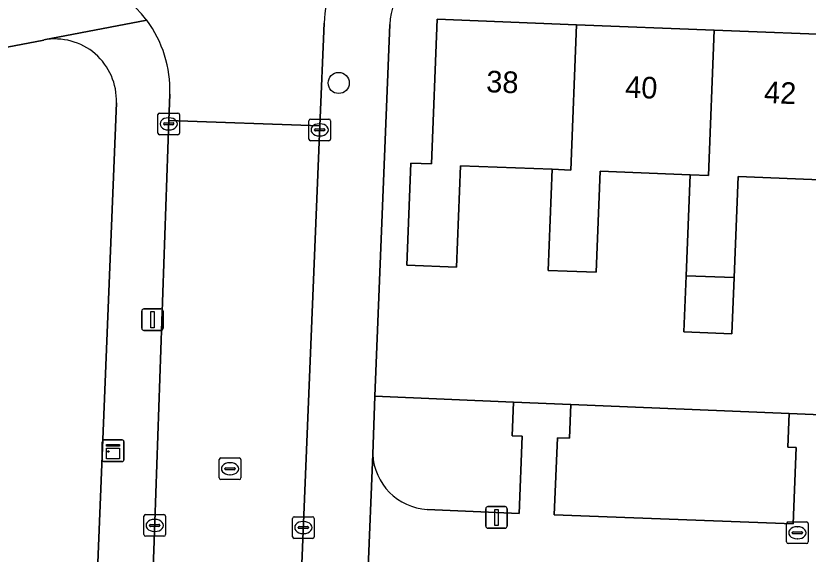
# Model space of a CAD drawing. Extents: x 160077 to 160948, y 386481 to 387498.
# Drawn here: x 160670.27 to 160706.93, y 386759.71 to 386784.61 of the extents above; entities that cross this region are included whole.
import ezdxf

# ---------------------------------------------------------------- set-up
doc = ezdxf.new("R2010")
doc.units = 0
for name, color, linetype in [('IMGEO_Boom', 7, 'Continuous'), ('IMGEO_Erf', 7, 'Continuous'), ('IMGEO_Groenvoorziening', 7, 'Continuous'), ('IMGEO_Kast', 7, 'Continuous'), ('IMGEO_Kolk', 7, 'Continuous'), ('IMGEO_Lichtmast', 7, 'Continuous'), ('IMGEO_Pand', 7, 'Continuous'), ('IMGEO_Pand_nummerreeks', 7, 'Continuous'), ('IMGEO_Rijbaan_lokaal_open', 7, 'Continuous'), ('IMGEO_Rioolput', 7, 'Continuous'), ('IMGEO_Voetpad_open', 7, 'Continuous')]:
    doc.layers.add(name, color=color, linetype=linetype)

msp = doc.modelspace()

# ---------------------------------------------------------------- linework, layer by layer
at = {"layer": 'IMGEO_Boom'}
msp.add_circle((160685.214, 386781.508), 0.489, dxfattribs=at)
at = {"layer": 'IMGEO_Erf'}
for points in [[(160707.857, 386777.016), (160703.69, 386777.179), (160703.506, 386772.502), (160703.404, 386769.907), (160701.185, 386769.994), (160701.287, 386772.588), (160701.47, 386777.264), (160697.303, 386777.427), (160697.119, 386772.75), (160695.776, 386772.802), (160694.9, 386772.836), (160695.083, 386777.512), (160690.847, 386777.678), (160690.663, 386772.991), (160688.367, 386773.081), (160688.55, 386777.798), (160689.499, 386777.761), (160689.76, 386784.455), (160696.221, 386784.203), (160702.59, 386783.955), (160708.959, 386783.707)], [(160687.571, 386784.21), (160686.882, 386767.017), (160693.294, 386766.741), (160695.949, 386766.63), (160706.046, 386766.21), (160708.637, 386766.106), (160727.336, 386765.387), (160726.211, 386772.948), (160726.016, 386772.942), (160716.258, 386773.261), (160714.11, 386773.331), (160714.131, 386773.869), (160709.963, 386774.033), (160709.893, 386772.254), (160708.514, 386772.307), (160707.674, 386772.34), (160707.857, 386777.016)], [(160671.565, 386783.492), (160627.292, 386775.05)], [(160624.696, 386772.042), (160624.053, 386756.457), (160635.418, 386756.081), (160656.069, 386755.397), (160656.152, 386757.908), (160661.06, 386757.745), (160665.846, 386757.587), (160665.763, 386755.076), (160673.888, 386754.75), (160674.925, 386780.592)]]:
    msp.add_lwpolyline(points, dxfattribs=at)
for centre, radius, start, end in [((160690.549, 386784.091), 2.981, 100.7384, 177.7207), ((160672.096, 386780.71), 2.832, 357.6061, 100.7993)]:
    msp.add_arc(centre, radius, start, end, dxfattribs=at)
at = {"layer": 'IMGEO_Groenvoorziening'}
for points in [[(160693.702, 386765.165), (160693.232, 386765.185), (160693.294, 386766.741), (160686.882, 386767.017), (160686.785, 386764.329)], [(160689.312, 386761.774), (160693.559, 386761.591), (160693.702, 386765.165)]]:
    msp.add_lwpolyline(points, dxfattribs=at)
msp.add_lwpolyline([(160695.949, 386766.63), (160695.887, 386765.074), (160695.33, 386765.097), (160695.187, 386761.53), (160706.234, 386761.114), (160706.375, 386764.638), (160705.984, 386764.654), (160706.046, 386766.21)], close=True, dxfattribs=at)
msp.add_arc((160689.475, 386764.462), 2.693, 182.8284, 266.5402, dxfattribs=at)
at = {"layer": 'IMGEO_Kast'}
for p, q in [((160674.276, 386764.068), (160674.276, 386764.909)), ((160674.276, 386764.909), (160674.276, 386764.068)), ((160674.351, 386764.993), (160675.192, 386764.993)), ((160675.192, 386764.993), (160674.351, 386764.993)), ((160675.276, 386764.918), (160675.276, 386764.077)), ((160675.276, 386764.077), (160675.276, 386764.918)), ((160675.201, 386763.993), (160674.36, 386763.993)), ((160674.36, 386763.993), (160675.201, 386763.993))]:
    msp.add_line(p, q, dxfattribs=at)
for points in [[(160674.471, 386764.783), (160675.071, 386764.783), (160675.071, 386764.698), (160674.471, 386764.698), (160674.471, 386764.783)], [(160674.471, 386764.608), (160675.071, 386764.608), (160675.071, 386764.119), (160674.471, 386764.119), (160674.471, 386764.608)]]:
    msp.add_lwpolyline(points, dxfattribs=at)
msp.add_circle((160674.555, 386764.457), 0.0377, dxfattribs=at)
for centre, start, end in [((160674.354, 386764.915), 92.4484, 184.2845), ((160674.354, 386764.915), 92.4484, 184.2845), ((160675.198, 386764.915), 2.4484, 94.2845), ((160675.198, 386764.915), 2.4484, 94.2845), ((160674.354, 386764.071), 182.4484, 274.2845), ((160674.354, 386764.071), 182.4484, 274.2845), ((160675.198, 386764.071), 272.4484, 4.2845), ((160675.198, 386764.071), 272.4484, 4.2845)]:
    msp.add_arc(centre, 0.0779, start, end, dxfattribs=at)
at = {"layer": 'IMGEO_Kolk'}
for p, q in [((160676.849, 386779.189), (160676.849, 386780.041)), ((160676.924, 386780.115), (160677.776, 386780.115)), ((160677.337, 386779.895), (160677.362, 386779.895)), ((160677.85, 386780.041), (160677.85, 386779.189)), ((160677.108, 386779.609), (160677.108, 386779.621)), ((160677.546, 386779.572), (160677.148, 386779.572)), ((160677.151, 386779.658), (160677.549, 386779.658)), ((160677.592, 386779.621), (160677.592, 386779.609)), ((160683.832, 386778.911), (160683.832, 386779.763)), ((160683.907, 386779.837), (160684.759, 386779.837)), ((160684.32, 386779.617), (160684.345, 386779.617)), ((160684.833, 386779.763), (160684.833, 386778.911)), ((160677.36, 386779.335), (160677.335, 386779.335)), ((160684.091, 386779.331), (160684.091, 386779.343)), ((160684.529, 386779.294), (160684.131, 386779.294)), ((160684.134, 386779.38), (160684.532, 386779.38)), ((160684.575, 386779.343), (160684.575, 386779.331)), ((160677.776, 386779.115), (160676.924, 386779.115)), ((160684.759, 386778.837), (160683.907, 386778.837)), ((160684.343, 386779.057), (160684.318, 386779.057)), ((160676.273, 386761.537), (160677.125, 386761.537)), ((160676.198, 386760.611), (160676.198, 386761.463)), ((160676.686, 386761.317), (160676.711, 386761.317)), ((160677.199, 386761.463), (160677.199, 386760.611)), ((160683.076, 386760.513), (160683.076, 386761.365)), ((160683.151, 386761.439), (160684.003, 386761.439)), ((160683.564, 386761.219), (160683.589, 386761.219)), ((160684.077, 386761.365), (160684.077, 386760.513)), ((160706.005, 386761.198), (160706.857, 386761.198)), ((160676.457, 386761.031), (160676.457, 386761.043)), ((160676.895, 386760.994), (160676.497, 386760.994)), ((160676.5, 386761.08), (160676.898, 386761.08)), ((160676.941, 386761.043), (160676.941, 386761.031)), ((160683.335, 386760.933), (160683.335, 386760.945)), ((160683.773, 386760.896), (160683.375, 386760.896)), ((160683.378, 386760.982), (160683.776, 386760.982)), ((160683.819, 386760.945), (160683.819, 386760.933)), ((160705.93, 386760.272), (160705.93, 386761.124)), ((160706.418, 386760.978), (160706.443, 386760.978)), ((160706.931, 386761.124), (160706.931, 386760.272)), ((160677.125, 386760.537), (160676.273, 386760.537)), ((160676.709, 386760.757), (160676.684, 386760.757)), ((160684.003, 386760.439), (160683.151, 386760.439)), ((160683.587, 386760.659), (160683.562, 386760.659)), ((160706.189, 386760.692), (160706.189, 386760.704)), ((160706.627, 386760.655), (160706.229, 386760.655)), ((160706.232, 386760.741), (160706.63, 386760.741)), ((160706.673, 386760.704), (160706.673, 386760.692)), ((160706.857, 386760.198), (160706.005, 386760.198)), ((160706.441, 386760.418), (160706.416, 386760.418))]:
    msp.add_line(p, q, dxfattribs=at)
for points in [[(160676.849, 386779.189), (160676.849, 386780.041)], [(160676.924, 386780.115), (160677.776, 386780.115)], [(160677.85, 386780.041), (160677.85, 386779.189)], [(160683.832, 386778.911), (160683.832, 386779.763)], [(160683.907, 386779.837), (160684.759, 386779.837)], [(160684.833, 386779.763), (160684.833, 386778.911)], [(160677.776, 386779.115), (160676.924, 386779.115)], [(160684.759, 386778.837), (160683.907, 386778.837)], [(160676.273, 386761.537), (160677.125, 386761.537)], [(160676.198, 386760.611), (160676.198, 386761.463)], [(160677.199, 386761.463), (160677.199, 386760.611)], [(160683.076, 386760.513), (160683.076, 386761.365)], [(160683.151, 386761.439), (160684.003, 386761.439)], [(160684.077, 386761.365), (160684.077, 386760.513)], [(160706.005, 386761.198), (160706.857, 386761.198)], [(160705.93, 386760.272), (160705.93, 386761.124)], [(160706.931, 386761.124), (160706.931, 386760.272)], [(160677.125, 386760.537), (160676.273, 386760.537)], [(160684.003, 386760.439), (160683.151, 386760.439)], [(160706.857, 386760.198), (160706.005, 386760.198)]]:
    msp.add_lwpolyline(points, dxfattribs=at)
for centre, radius, start, end in [((160676.926, 386780.039), 0.0765, 91.552, 178.448), ((160676.926, 386780.039), 0.0765, 91.552, 178.448), ((160677.774, 386780.039), 0.0765, 1.552, 88.448), ((160677.774, 386780.039), 0.0765, 1.552, 88.448), ((160677.148, 386779.618), 0.0403, 85.8775, 175.7526), ((160677.145, 386779.608), 0.0366, 178.938, 274.7102), ((160677.549, 386779.615), 0.043, 264.8664, 352.4533), ((160677.553, 386779.62), 0.0386, 1.7309, 96.639), ((160683.909, 386779.761), 0.0765, 91.552, 178.448), ((160683.909, 386779.761), 0.0765, 91.552, 178.448), ((160684.757, 386779.761), 0.0765, 1.552, 88.448), ((160684.757, 386779.761), 0.0765, 1.552, 88.448), ((160676.926, 386779.191), 0.0765, 181.552, 268.448), ((160676.926, 386779.191), 0.0765, 181.552, 268.448), ((160677.774, 386779.191), 0.0765, 271.552, 358.448), ((160677.774, 386779.191), 0.0765, 271.552, 358.448), ((160684.131, 386779.34), 0.0403, 85.8775, 175.7526), ((160684.128, 386779.33), 0.0366, 178.938, 274.7102), ((160684.532, 386779.337), 0.043, 264.8664, 352.4533), ((160684.536, 386779.342), 0.0386, 1.7309, 96.639), ((160683.909, 386778.913), 0.0765, 181.552, 268.448), ((160683.909, 386778.913), 0.0765, 181.552, 268.448), ((160684.757, 386778.913), 0.0765, 271.552, 358.448), ((160684.757, 386778.913), 0.0765, 271.552, 358.448), ((160676.275, 386761.461), 0.0765, 91.552, 178.448), ((160676.275, 386761.461), 0.0765, 91.552, 178.448), ((160677.123, 386761.461), 0.0765, 1.552, 88.448), ((160677.123, 386761.461), 0.0765, 1.552, 88.448), ((160683.153, 386761.363), 0.0765, 91.552, 178.448), ((160683.153, 386761.363), 0.0765, 91.552, 178.448), ((160684.001, 386761.363), 0.0765, 1.552, 88.448), ((160684.001, 386761.363), 0.0765, 1.552, 88.448), ((160706.007, 386761.122), 0.0765, 91.552, 178.448), ((160706.007, 386761.122), 0.0765, 91.552, 178.448), ((160706.855, 386761.122), 0.0765, 1.552, 88.448), ((160706.855, 386761.122), 0.0765, 1.552, 88.448), ((160676.497, 386761.04), 0.0403, 85.8775, 175.7526), ((160676.494, 386761.03), 0.0366, 178.938, 274.7102), ((160676.898, 386761.037), 0.043, 264.8664, 352.4533), ((160676.902, 386761.042), 0.0386, 1.7309, 96.639), ((160683.375, 386760.942), 0.0403, 85.8775, 175.7526), ((160683.372, 386760.932), 0.0366, 178.938, 274.7102), ((160683.776, 386760.939), 0.043, 264.8664, 352.4533), ((160683.78, 386760.944), 0.0386, 1.7309, 96.639), ((160676.275, 386760.613), 0.0765, 181.552, 268.448), ((160676.275, 386760.613), 0.0765, 181.552, 268.448), ((160677.123, 386760.613), 0.0765, 271.552, 358.448), ((160677.123, 386760.613), 0.0765, 271.552, 358.448), ((160683.153, 386760.515), 0.0765, 181.552, 268.448), ((160683.153, 386760.515), 0.0765, 181.552, 268.448), ((160684.001, 386760.515), 0.0765, 271.552, 358.448), ((160684.001, 386760.515), 0.0765, 271.552, 358.448), ((160706.229, 386760.701), 0.0403, 85.8775, 175.7526), ((160706.226, 386760.691), 0.0366, 178.938, 274.7102), ((160706.63, 386760.698), 0.043, 264.8664, 352.4533), ((160706.634, 386760.703), 0.0386, 1.7309, 96.639), ((160706.007, 386760.274), 0.0765, 181.552, 268.448), ((160706.007, 386760.274), 0.0765, 181.552, 268.448), ((160706.855, 386760.274), 0.0765, 271.552, 358.448), ((160706.855, 386760.274), 0.0765, 271.552, 358.448)]:
    msp.add_arc(centre, radius, start, end, dxfattribs=at)
for centre, major_axis, ratio, start_param, end_param in [((160677.336, 386779.615), (-0.387, 0.002), 0.722429, 4.712389, 7.853982), ((160677.361, 386779.615), (-0.39, 0.002), 0.717154, 1.570796, 4.712389), ((160684.319, 386779.337), (-0.387, 0.002), 0.722429, 4.712389, 7.853982), ((160684.344, 386779.337), (-0.39, 0.002), 0.717154, 1.570796, 4.712389), ((160676.685, 386761.037), (-0.387, 0.002), 0.722429, 4.712389, 7.853982), ((160676.71, 386761.037), (-0.39, 0.002), 0.717154, 1.570796, 4.712389), ((160683.563, 386760.939), (-0.387, 0.002), 0.722429, 4.712389, 7.853982), ((160683.588, 386760.939), (-0.39, 0.002), 0.717154, 1.570796, 4.712389), ((160706.417, 386760.698), (-0.387, 0.002), 0.722429, 4.712389, 7.853982), ((160706.442, 386760.698), (-0.39, 0.002), 0.717154, 1.570796, 4.712389)]:
    msp.add_ellipse(centre, major_axis=major_axis, ratio=ratio, start_param=start_param, end_param=end_param, dxfattribs=at)
at = {"layer": 'IMGEO_Lichtmast'}
for p, q in [((160676.2, 386771.057), (160676.99, 386771.057)), ((160676.99, 386771.057), (160676.2, 386771.057)), ((160676.1, 386770.157), (160676.1, 386770.957)), ((160676.1, 386770.957), (160676.1, 386770.157)), ((160677.09, 386770.957), (160677.09, 386770.157)), ((160677.09, 386770.157), (160677.09, 386770.957)), ((160676.99, 386770.057), (160676.2, 386770.057)), ((160676.2, 386770.057), (160676.99, 386770.057)), ((160692.116, 386761.906), (160692.906, 386761.906)), ((160692.906, 386761.906), (160692.116, 386761.906)), ((160692.016, 386761.006), (160692.016, 386761.806)), ((160692.016, 386761.806), (160692.016, 386761.006)), ((160693.006, 386761.806), (160693.006, 386761.006)), ((160693.006, 386761.006), (160693.006, 386761.806)), ((160692.906, 386760.906), (160692.116, 386760.906)), ((160692.116, 386760.906), (160692.906, 386760.906))]:
    msp.add_line(p, q, dxfattribs=at)
for points in [[(160676.52, 386770.932), (160676.67, 386770.932), (160676.67, 386770.182), (160676.52, 386770.182), (160676.52, 386770.932)], [(160692.436, 386761.781), (160692.586, 386761.781), (160692.586, 386761.031), (160692.436, 386761.031), (160692.436, 386761.781)]]:
    msp.add_lwpolyline(points, dxfattribs=at)
for centre, start, end in [((160676.2, 386770.957), 90, 180), ((160676.2, 386770.957), 90, 180), ((160676.99, 386770.957), 0, 90), ((160676.99, 386770.957), 360, 90), ((160676.2, 386770.157), 180, 270), ((160676.2, 386770.157), 180, 270), ((160676.99, 386770.157), 270, 0), ((160676.99, 386770.157), 270, 0), ((160692.116, 386761.806), 90, 180), ((160692.116, 386761.806), 90, 180), ((160692.906, 386761.806), 0, 90), ((160692.906, 386761.806), 360, 90), ((160692.116, 386761.006), 180, 270), ((160692.116, 386761.006), 180, 270), ((160692.906, 386761.006), 270, 0), ((160692.906, 386761.006), 270, 0)]:
    msp.add_arc(centre, 0.1, start, end, dxfattribs=at)
at = {"layer": 'IMGEO_Pand'}
for points in [[(160695.083, 386777.512), (160695.959, 386777.478), (160696.221, 386784.203), (160689.76, 386784.455), (160689.499, 386777.761), (160688.55, 386777.798), (160688.367, 386773.081), (160690.663, 386772.991), (160690.847, 386777.678)], [(160695.776, 386772.802), (160697.119, 386772.75), (160697.303, 386777.427), (160701.47, 386777.264), (160702.328, 386777.23), (160702.59, 386783.955), (160696.221, 386784.203), (160695.959, 386777.478), (160695.083, 386777.512), (160694.9, 386772.836)], [(160708.959, 386783.707), (160702.59, 386783.955), (160702.328, 386777.23), (160701.47, 386777.264), (160701.287, 386772.588), (160703.506, 386772.502), (160703.69, 386777.179), (160707.857, 386777.016), (160708.697, 386776.983)], [(160703.506, 386772.502), (160701.287, 386772.588), (160701.185, 386769.994), (160703.404, 386769.907)]]:
    msp.add_lwpolyline(points, close=True, dxfattribs=at)
at = {"layer": 'IMGEO_Rijbaan_lokaal_open'}
for points in [[(160677.399, 386780.99), (160677.356, 386779.776), (160684.339, 386779.52), (160684.534, 386784.274)], [(160680.523, 386684.347), (160681.081, 386699.432), (160682.253, 386727.666), (160683.133, 386750), (160683.261, 386753.26), (160684.339, 386779.52), (160677.356, 386779.776), (160676.66, 386759.882), (160676.246, 386750), (160675.458, 386731.188), (160674.211, 386700.474), (160673.381, 386679.573), (160672.381, 386653.071), (160671.034, 386622.001)]]:
    msp.add_lwpolyline(points, dxfattribs=at)
for centre, radius, start, end in [((160671.991, 386781.179), 5.41, 36.6018, 100.8931), ((160690.676, 386784.014), 6.147, 160.7553, 177.5747), ((160671.986, 386781.177), 5.416, 358.0244, 36.5861)]:
    msp.add_arc(centre, radius, start, end, dxfattribs=at)
at = {"layer": 'IMGEO_Rioolput'}
for p, q in [((160679.757, 386764.16), (160680.609, 386764.16)), ((160679.682, 386763.234), (160679.682, 386764.086)), ((160680.17, 386763.94), (160680.195, 386763.94)), ((160680.683, 386764.086), (160680.683, 386763.234)), ((160679.941, 386763.654), (160679.941, 386763.666)), ((160680.379, 386763.617), (160679.981, 386763.617)), ((160679.984, 386763.703), (160680.382, 386763.703)), ((160680.193, 386763.38), (160680.168, 386763.38)), ((160680.425, 386763.666), (160680.425, 386763.654)), ((160680.609, 386763.16), (160679.757, 386763.16))]:
    msp.add_line(p, q, dxfattribs=at)
for points in [[(160679.757, 386764.16), (160680.609, 386764.16)], [(160679.682, 386763.234), (160679.682, 386764.086)], [(160680.683, 386764.086), (160680.683, 386763.234)], [(160680.609, 386763.16), (160679.757, 386763.16)]]:
    msp.add_lwpolyline(points, dxfattribs=at)
for centre, radius, start, end in [((160679.759, 386764.084), 0.0765, 91.552, 178.448), ((160679.759, 386764.084), 0.0765, 91.552, 178.448), ((160680.607, 386764.084), 0.0765, 1.552, 88.448), ((160680.607, 386764.084), 0.0765, 1.552, 88.448), ((160679.981, 386763.663), 0.0403, 85.8775, 175.7526), ((160679.978, 386763.653), 0.0366, 178.938, 274.7102), ((160680.382, 386763.66), 0.043, 264.8664, 352.4533), ((160680.386, 386763.665), 0.0386, 1.7309, 96.639), ((160679.759, 386763.236), 0.0765, 181.552, 268.448), ((160679.759, 386763.236), 0.0765, 181.552, 268.448), ((160680.607, 386763.236), 0.0765, 271.552, 358.448), ((160680.607, 386763.236), 0.0765, 271.552, 358.448)]:
    msp.add_arc(centre, radius, start, end, dxfattribs=at)
for centre, major_axis, ratio, start_param, end_param in [((160680.169, 386763.66), (-0.387, 0.002), 0.722429, 4.712389, 7.853982), ((160680.194, 386763.66), (-0.39, 0.002), 0.717154, 1.570796, 4.712389)]:
    msp.add_ellipse(centre, major_axis=major_axis, ratio=ratio, start_param=start_param, end_param=end_param, dxfattribs=at)
at = {"layer": 'IMGEO_Voetpad_open'}
for points in [[(160671.565, 386783.492), (160671.575, 386783.507), (160676.335, 386784.405)], [(160676.335, 386784.405), (160671.575, 386783.507), (160671.565, 386783.492)], [(160684.534, 386784.274), (160684.339, 386779.52), (160683.261, 386753.26), (160683.133, 386750), (160682.253, 386727.666), (160681.081, 386699.432), (160680.523, 386684.347)], [(160685.594, 386735.085), (160685.681, 386737.217), (160686.202, 386750), (160686.557, 386758.725), (160686.785, 386764.329), (160686.882, 386767.017), (160687.571, 386784.21)], [(160627.292, 386775.05), (160671.565, 386783.492)], [(160673.381, 386679.573), (160674.211, 386700.474), (160675.458, 386731.188), (160676.246, 386750), (160676.66, 386759.882), (160677.356, 386779.776), (160677.399, 386780.99)], [(160674.925, 386780.592), (160673.888, 386754.75), (160673.824, 386753.158), (160673.697, 386750), (160671.348, 386691.449), (160671.289, 386689.993), (160668.563, 386622.044)], [(160725.088, 386760.391), (160707.892, 386761.052), (160708.034, 386764.572), (160708.575, 386764.55), (160708.637, 386766.106), (160706.046, 386766.21), (160705.984, 386764.654), (160706.375, 386764.638), (160706.234, 386761.114), (160695.187, 386761.53), (160695.33, 386765.097), (160695.887, 386765.074), (160695.949, 386766.63), (160693.294, 386766.741), (160693.232, 386765.185), (160693.702, 386765.165), (160693.559, 386761.591), (160689.312, 386761.774)], [(160686.785, 386764.329), (160686.557, 386758.725), (160728.639, 386757.007), (160727.675, 386763.262), (160727.652, 386763.274)]]:
    msp.add_lwpolyline(points, dxfattribs=at)
for centre, radius, start, end in [((160690.549, 386784.091), 2.981, 100.7384, 177.7207), ((160671.991, 386781.179), 5.41, 36.6018, 100.8931), ((160690.676, 386784.014), 6.147, 160.7553, 177.5747), ((160671.986, 386781.177), 5.416, 358.0244, 36.5861), ((160672.096, 386780.71), 2.832, 357.6061, 100.7993), ((160689.475, 386764.462), 2.693, 182.8284, 266.5402)]:
    msp.add_arc(centre, radius, start, end, dxfattribs=at)

# ---------------------------------------------------------------- texts
at = {"layer": 'IMGEO_Pand_nummerreeks'}
for s, rotation, p in [('38', 357.7674, (160692.024, 386781.084)), ('40', 357.7674, (160698.452, 386780.833)), ('42', 357.7655, (160704.874, 386780.583))]:
    msp.add_text(s, height=1, rotation=rotation, dxfattribs=at).set_placement(p)

doc.saveas('drawing.dxf')
